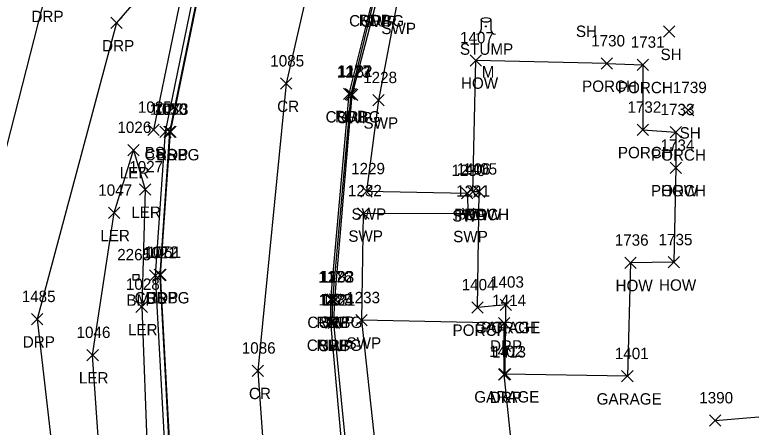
# Model space of a CAD drawing. Extents: x 462930 to 463548, y 29607 to 30453.
# Drawn here: x 463320.55 to 463360, y 30081.35 to 30103.46 of the extents above; entities that cross this region are included whole.
import ezdxf

# ---------------------------------------------------------------- set-up
doc = ezdxf.new("R2010")
doc.units = 0
for name, color, linetype in [('C_A', 7, 'Continuous'), ('C_I', 7, 'Continuous'), ('CPBM', 7, 'Continuous'), ('L_A', 7, 'Continuous'), ('L_C', 7, 'Continuous'), ('L_I', 7, 'Continuous'), ('L_TIC', 7, 'Continuous'), ('LAHR', 7, 'Continuous'), ('LARO', 7, 'Continuous'), ('LBC', 7, 'Continuous'), ('LBF', 7, 'Continuous'), ('LELB', 7, 'Continuous'), ('LTS', 7, 'Continuous'), ('P_A', 7, 'Continuous'), ('P_I', 7, 'Continuous'), ('P_TIC', 7, 'Continuous'), ('PET', 7, 'Continuous'), ('PRC', 7, 'Continuous'), ('R_A', 7, 'Continuous'), ('R_I', 7, 'Continuous'), ('R_TIC', 7, 'Continuous'), ('RC', 7, 'Continuous'), ('RDP', 7, 'Continuous'), ('RSW', 7, 'Continuous')]:
    doc.layers.add(name, color=color, linetype=linetype)

msp = doc.modelspace()

# ---------------------------------------------------------------- linework, layer by layer
at = {"layer": 'CPBM'}
for p, q in [((463326.897, 30089.234), (463326.897, 30089.539)), ((463326.897, 30089.539), (463327.202, 30089.539)), ((463327.05, 30089.387), (463327.05, 30089.387)), ((463327.05, 30089.387), (463327.05, 30089.387)), ((463327.202, 30089.539), (463327.202, 30089.234)), ((463327.202, 30089.234), (463326.897, 30089.234))]:
    msp.add_line(p, q, dxfattribs=at)
at = {"layer": 'L_TIC'}
for points in [[(463355.299, 30102.249), (463355.909, 30102.859)], [(463355.909, 30102.249), (463355.299, 30102.859)], [(463344.945, 30100.709), (463345.555, 30101.319)], [(463345.555, 30100.709), (463344.945, 30101.319)], [(463351.97, 30100.543), (463352.58, 30101.153)], [(463352.58, 30100.543), (463351.97, 30101.153)], [(463353.889, 30100.472), (463354.499, 30101.082)], [(463354.499, 30100.472), (463353.889, 30101.082)], [(463356.324, 30098.042), (463356.934, 30098.652)], [(463356.934, 30098.042), (463356.324, 30098.652)], [(463327.689, 30096.984), (463328.299, 30097.594)], [(463328.299, 30096.984), (463327.689, 30097.594)], [(463353.888, 30096.988), (463354.498, 30097.598)], [(463354.498, 30096.988), (463353.888, 30097.598)], [(463328.322, 30096.879), (463328.932, 30097.489)], [(463328.932, 30096.879), (463328.322, 30097.489)], [(463355.662, 30096.859), (463356.272, 30097.469)], [(463356.272, 30096.859), (463355.662, 30097.469)], [(463326.609, 30095.904), (463327.219, 30096.514)], [(463327.219, 30095.904), (463326.609, 30096.514)], [(463355.66, 30094.946), (463356.27, 30095.556)], [(463356.27, 30094.946), (463355.66, 30095.556)], [(463355.66, 30094.946), (463356.27, 30095.556)], [(463356.27, 30094.946), (463355.66, 30095.556)], [(463327.228, 30093.792), (463327.838, 30094.402)], [(463327.838, 30093.792), (463327.228, 30094.402)], [(463344.785, 30093.669), (463345.395, 30094.279)], [(463345.395, 30093.669), (463344.785, 30094.279)], [(463345.118, 30093.673), (463345.728, 30094.283)], [(463345.728, 30093.673), (463345.118, 30094.283)], [(463345.118, 30093.673), (463345.728, 30094.283)], [(463345.728, 30093.673), (463345.118, 30094.283)], [(463325.568, 30092.541), (463326.178, 30093.151)], [(463326.178, 30092.541), (463325.568, 30093.151)], [(463355.555, 30089.889), (463356.165, 30090.499)], [(463356.165, 30089.889), (463355.555, 30090.499)], [(463353.224, 30089.864), (463353.834, 30090.474)], [(463353.834, 30089.864), (463353.224, 30090.474)], [(463327.781, 30089.182), (463328.391, 30089.792)], [(463328.391, 30089.182), (463327.781, 30089.792)], [(463346.553, 30087.615), (463347.163, 30088.225)], [(463347.163, 30087.615), (463346.553, 30088.225)], [(463346.553, 30087.615), (463347.163, 30088.225)], [(463347.163, 30087.615), (463346.553, 30088.225)], [(463327.049, 30087.499), (463327.659, 30088.109)], [(463327.659, 30087.499), (463327.049, 30088.109)], [(463345.033, 30087.471), (463345.643, 30088.081)], [(463345.643, 30087.471), (463345.033, 30088.081)], [(463324.422, 30084.919), (463325.032, 30085.529)], [(463325.032, 30084.919), (463324.422, 30085.529)], [(463346.509, 30083.898), (463347.119, 30084.508)], [(463347.119, 30083.898), (463346.509, 30084.508)], [(463353.062, 30083.787), (463353.672, 30084.397)], [(463353.672, 30083.787), (463353.062, 30084.397)], [(463357.76, 30081.414), (463358.37, 30082.024)], [(463358.37, 30081.414), (463357.76, 30082.024)]]:
    msp.add_lwpolyline(points, dxfattribs=at)
at = {"layer": 'LAHR'}
msp.add_lwpolyline([(463358.065, 30081.719), (463367.2, 30082.486)], dxfattribs=at)
at = {"layer": 'LARO'}
for points in [[(463325.873, 30092.846), (463326.914, 30096.209)], [(463326.914, 30096.209), (463327.533, 30094.097), (463327.354, 30087.804), (463327.66, 30079.621), (463329.744, 30068.213), (463329.537, 30065.888), (463331.712, 30059.015), (463332.481, 30053.119), (463334.222, 30044.659), (463330.985, 30039.873), (463329.046, 30039.945), (463328.631, 30049.54), (463329.172, 30060.23), (463327.01, 30065.344)], [(463325.38, 30075.731), (463324.727, 30085.224), (463325.873, 30092.846)]]:
    msp.add_lwpolyline(points, dxfattribs=at)
at = {"layer": 'LBC'}
for points in [[(463345.423, 30093.978), (463345.09, 30093.974), (463345.25, 30101.014)], [(463355.965, 30095.251), (463355.86, 30090.194), (463353.529, 30090.169)], [(463353.529, 30090.169), (463353.367, 30084.092)], [(463353.367, 30084.092), (463346.814, 30084.203), (463346.858, 30087.92)]]:
    msp.add_lwpolyline(points, dxfattribs=at)
at = {"layer": 'LBF'}
for points in [[(463352.275, 30100.848), (463345.25, 30101.014)], [(463352.275, 30100.848), (463354.194, 30100.777), (463354.193, 30097.293), (463355.967, 30097.164), (463355.965, 30095.251)], [(463346.858, 30087.92), (463345.338, 30087.776), (463345.423, 30093.978)]]:
    msp.add_lwpolyline(points, dxfattribs=at)
at = {"layer": 'LELB'}
msp.add_lwpolyline([(463338.373, 30022.22), (463340.767, 30011.24), (463345.965, 29995.767), (463346.937, 29987.36), (463347.521, 29987.525), (463346.646, 29996.093), (463342.063, 30011.435), (463339.344, 30022.565), (463336.301, 30037.573), (463333.414, 30053.384), (463330.633, 30068.275), (463328.629, 30079.728), (463328.086, 30089.487), (463328.627, 30097.184), (463330.299, 30105.361), (463329.682, 30105.522), (463327.994, 30097.289)], dxfattribs=at)
at = {"layer": 'LTS'}
for p, q in [((463345.54, 30103.184), (463345.54, 30102.676)), ((463346.048, 30103.134), (463346.048, 30103.184)), ((463346.048, 30103.184), (463346.048, 30102.676)), ((463345.794, 30102.836), (463345.794, 30102.836)), ((463345.794, 30102.836), (463345.794, 30102.836)), ((463345.794, 30102.829), (463345.794, 30102.829))]:
    msp.add_line(p, q, dxfattribs=at)
msp.add_circle((463345.794, 30102.836), 0.0254, dxfattribs=at)
for centre, start, end in [((463345.286, 30102.676), 270, 360), ((463346.302, 30102.676), 180, 270)]:
    msp.add_arc(centre, 0.254, start, end, dxfattribs=at)
msp.add_ellipse((463345.794, 30103.184), major_axis=(-0.254, 0), ratio=0.5, dxfattribs=at)
at = {"layer": 'P_TIC'}
for points in [[(463334.782, 30099.466), (463335.392, 30100.076)], [(463335.392, 30099.466), (463334.782, 30100.076)], [(463338.169, 30098.921), (463338.779, 30099.531)], [(463338.779, 30098.921), (463338.169, 30099.531)], [(463328.587, 30096.878), (463329.197, 30097.488)], [(463329.197, 30096.878), (463328.587, 30097.488)], [(463328.052, 30089.217), (463328.662, 30089.827)], [(463328.662, 30089.217), (463328.052, 30089.827)], [(463337.174, 30087.891), (463337.784, 30088.501)], [(463337.784, 30087.891), (463337.174, 30088.501)], [(463337.175, 30086.663), (463337.785, 30087.273)], [(463337.785, 30086.663), (463337.175, 30087.273)], [(463333.271, 30084.08), (463333.881, 30084.69)], [(463333.881, 30084.08), (463333.271, 30084.69)]]:
    msp.add_lwpolyline(points, dxfattribs=at)
at = {"layer": 'PET'}
for points in [[(463374.338, 29956.391), (463367.555, 29969.533), (463365.556, 29974.625), (463364.583, 29976.896), (463356.695, 29995.475), (463352.505, 30009.098), (463350.167, 30017.966), (463347.98, 30027.115), (463347.733, 30028.32), (463346.051, 30037.294), (463343.907, 30048.483), (463342.761, 30054.643), (463342.551, 30055.85), (463341.301, 30062.483), (463338.432, 30077.399), (463338.227, 30078.623), (463337.48, 30086.968), (463337.479, 30088.196), (463338.474, 30099.226), (463339.751, 30104.374), (463341.961, 30110.783)], [(463349.052, 29990.82), (463346.99, 29996.409), (463342.314, 30011.546), (463339.633, 30022.646), (463336.631, 30037.644), (463333.669, 30053.397), (463330.887, 30068.339), (463328.89, 30079.76), (463328.357, 30089.522), (463328.892, 30097.183), (463330.561, 30105.3)]]:
    msp.add_lwpolyline(points, dxfattribs=at)
at = {"layer": 'PRC'}
msp.add_lwpolyline([(463337.978, 30112.385), (463335.087, 30099.771), (463333.576, 30084.385), (463334.686, 30068.796), (463337.03, 30053.748), (463339.908, 30038.01), (463343.632, 30023.045), (463346.617, 30012.904), (463351.044, 29997.524), (463354.76, 29987.177), (463360.584, 29974.202), (463367.548, 29960.534), (463374.695, 29948.349)], dxfattribs=at)
at = {"layer": 'R_TIC'}
for points in [[(463325.696, 30102.715), (463326.306, 30103.325)], [(463326.306, 30102.715), (463325.696, 30103.325)], [(463338.245, 30098.902), (463338.855, 30099.512)], [(463338.855, 30098.902), (463338.245, 30099.512)], [(463338.325, 30098.865), (463338.935, 30099.475)], [(463338.935, 30098.865), (463338.325, 30099.475)], [(463339.733, 30098.574), (463340.343, 30099.184)], [(463340.343, 30098.574), (463339.733, 30099.184)], [(463328.546, 30096.874), (463329.156, 30097.484)], [(463329.156, 30096.874), (463328.546, 30097.484)], [(463339.089, 30093.692), (463339.699, 30094.302)], [(463339.699, 30093.692), (463339.089, 30094.302)], [(463344.485, 30093.597), (463345.095, 30094.207)], [(463345.095, 30093.597), (463344.485, 30094.207)], [(463338.92, 30092.511), (463339.53, 30093.121)], [(463339.53, 30092.511), (463338.92, 30093.121)], [(463344.537, 30092.489), (463345.147, 30093.099)], [(463345.147, 30092.489), (463344.537, 30093.099)], [(463328.014, 30089.208), (463328.624, 30089.818)], [(463328.624, 30089.208), (463328.014, 30089.818)], [(463337.268, 30087.891), (463337.878, 30088.501)], [(463337.878, 30087.891), (463337.268, 30088.501)], [(463337.402, 30087.899), (463338.012, 30088.509)], [(463338.012, 30087.899), (463337.402, 30088.509)], [(463321.445, 30086.843), (463322.055, 30087.453)], [(463322.055, 30086.843), (463321.445, 30087.453)], [(463338.823, 30086.782), (463339.433, 30087.392)], [(463339.433, 30086.782), (463338.823, 30087.392)], [(463337.24, 30086.663), (463337.85, 30087.273)], [(463337.85, 30086.663), (463337.24, 30087.273)], [(463337.338, 30086.642), (463337.948, 30087.252)], [(463337.948, 30086.642), (463337.338, 30087.252)], [(463346.471, 30086.626), (463347.081, 30087.236)], [(463347.081, 30086.626), (463346.471, 30087.236)], [(463346.465, 30083.871), (463347.075, 30084.481)], [(463347.075, 30083.871), (463346.465, 30084.481)]]:
    msp.add_lwpolyline(points, dxfattribs=at)
at = {"layer": 'RC'}
for points in [[(463341.996, 30110.77), (463339.811, 30104.355), (463338.55, 30099.207), (463337.573, 30088.196), (463337.545, 30086.968)], [(463330.433, 30105.335), (463330.506, 30105.311), (463328.851, 30097.179), (463328.319, 30089.513), (463328.85, 30079.744), (463330.845, 30068.328), (463333.629, 30053.397), (463336.583, 30037.649), (463339.548, 30022.613), (463342.224, 30011.501), (463346.871, 29996.398), (463346.791, 29996.353)]]:
    msp.add_lwpolyline(points, dxfattribs=at)
at = {"layer": 'RDP'}
for points in [[(463319.513, 30094.018), (463322.216, 30104.589), (463322.678, 30111.184), (463317.965, 30116.023), (463310.345, 30118.227), (463299.708, 30118.434), (463291.709, 30117.924)], [(463329.61, 30107.203), (463326.001, 30103.02), (463321.75, 30087.148), (463322.748, 30078.455), (463323.504, 30066.246), (463318.638, 30068.319), (463319.452, 30074.807), (463317.191, 30075.893), (463318.57, 30082.354), (463317.087, 30083.2)], [(463346.776, 30086.931), (463339.128, 30087.087)], [(463347.244, 30079.588), (463346.77, 30084.176), (463346.776, 30086.931)]]:
    msp.add_lwpolyline(points, dxfattribs=at)
at = {"layer": 'RSW'}
for points in [[(463342.697, 30055.906), (463341.529, 30062.506), (463341.211, 30063.796), (463339.622, 30072.17), (463338.628, 30077.431), (463338.465, 30078.663), (463337.643, 30086.947), (463337.707, 30088.204), (463338.63, 30099.17), (463339.961, 30104.318)], [(463340.994, 30103.946), (463340.038, 30098.879), (463339.394, 30093.997), (463344.79, 30093.902), (463344.842, 30092.794), (463339.225, 30092.816), (463339.128, 30087.087), (463340.013, 30078.853), (463340.331, 30075.79), (463340.629, 30074.836), (463341.063, 30072.45), (463344.869, 30072.982), (463344.993, 30071.83), (463341.3, 30071.156), (463343.219, 30061.394), (463344.068, 30056.729)]]:
    msp.add_lwpolyline(points, dxfattribs=at)

# ---------------------------------------------------------------- texts
at = {"layer": 'C_A'}
msp.add_text('BM', height=0.6096, dxfattribs=at).set_placement((463326.536, 30087.863))
at = {"layer": 'C_I'}
msp.add_text('2265', height=0.6096, dxfattribs=at).set_placement((463326.042, 30090.301))
at = {"layer": 'L_A'}
for s, p in [('SH', (463350.612, 30102.268)), ('STUMP', (463344.399, 30101.313)), ('SH', (463355.143, 30101.03)), ('HOW', (463344.453, 30099.49)), ('PORCH', (463350.941, 30099.324)), ('PORCH', (463352.86, 30099.253)), ('SH', (463356.168, 30096.823)), ('BS', (463327.519, 30095.765)), ('BS', (463328.152, 30095.66)), ('PORCH', (463352.859, 30095.769)), ('PORCH', (463354.633, 30095.64)), ('LER', (463326.177, 30094.685)), ('PORCH', (463354.631, 30093.727)), ('HOW', (463355.168, 30093.727)), ('LER', (463326.796, 30092.573)), ('PORCH', (463344.089, 30092.454)), ('HOW', (463344.293, 30092.45)), ('HOW', (463344.626, 30092.454)), ('LER', (463325.136, 30091.322)), ('HOW', (463352.732, 30088.645)), ('HOW', (463355.063, 30088.67)), ('BS', (463327.611, 30087.963)), ('GARAGE', (463345.212, 30086.396)), ('PORCH', (463345.524, 30086.396)), ('LER', (463326.617, 30086.28)), ('PORCH', (463344.004, 30086.252)), ('LER', (463323.99, 30083.7)), ('GARAGE', (463345.168, 30082.679)), ('GARAGE', (463351.721, 30082.568))]:
    msp.add_text(s, height=0.6096, dxfattribs=at).set_placement(p)
at = {"layer": 'L_C'}
msp.add_text('M', height=0.61, dxfattribs=at).set_placement((463345.567, 30100.094))
at = {"layer": 'L_I'}
for s, p in [('1407', (463344.405, 30101.928)), ('1730', (463351.428, 30101.762)), ('1731', (463353.546, 30101.691)), ('1739', (463355.806, 30099.261)), ('1025', (463327.149, 30098.203)), ('1732', (463353.372, 30098.207)), ('1022', (463327.782, 30098.098)), ('1733', (463355.146, 30098.078)), ('1026', (463326.052, 30097.123)), ('1734', (463355.144, 30096.165)), ('1734', (463355.144, 30096.165)), ('1027', (463326.688, 30095.011)), ('1406', (463344.228, 30094.888)), ('1405', (463344.578, 30094.892)), ('1405', (463344.578, 30094.892)), ('1047', (463325.028, 30093.76)), ('1736', (463352.691, 30091.083)), ('1735', (463355.039, 30091.108)), ('1021', (463327.414, 30090.401)), ('1028', (463326.509, 30088.718)), ('1404', (463344.493, 30088.69)), ('1403', (463346.013, 30088.834)), ('1403', (463346.013, 30088.834)), ('1046', (463323.865, 30086.138)), ('1402', (463345.969, 30085.117)), ('1401', (463352.695, 30085.006)), ('1390', (463357.218, 30082.633))]:
    msp.add_text(s, height=0.6096, dxfattribs=at).set_placement(p)
at = {"layer": 'P_A'}
for s, p in [('RDP', (463338.985, 30102.85)), ('CR', (463334.609, 30098.247)), ('RDP', (463337.708, 30097.702)), ('RDP', (463328.126, 30095.659)), ('RDP', (463327.591, 30087.998)), ('RDP', (463336.713, 30086.672)), ('RDP', (463336.714, 30085.444)), ('CR', (463333.098, 30082.861))]:
    msp.add_text(s, height=0.6096, dxfattribs=at).set_placement(p)
at = {"layer": 'P_I'}
for s, p in [('1085', (463334.242, 30100.685)), ('1177', (463337.826, 30100.14)), ('1073', (463328.047, 30098.097)), ('1072', (463327.512, 30090.436)), ('1176', (463336.814, 30089.11)), ('1175', (463336.832, 30087.882)), ('1086', (463332.714, 30085.299))]:
    msp.add_text(s, height=0.6096, dxfattribs=at).set_placement(p)
at = {"layer": 'R_A'}
for s, p in [('DRP', (463321.45, 30103.065)), ('CURBG', (463338.465, 30102.831)), ('SWP', (463339.157, 30102.794)), ('SWP', (463340.19, 30102.422)), ('DRP', (463325.235, 30101.496)), ('CURBG', (463337.204, 30097.683)), ('SWP', (463337.826, 30097.646)), ('SWP', (463339.234, 30097.355)), ('CURBG', (463327.505, 30095.655)), ('SWP', (463338.59, 30092.473)), ('SWP', (463343.986, 30092.378)), ('SWP', (463338.421, 30091.292)), ('SWP', (463344.038, 30091.27)), ('CURBG', (463326.973, 30087.989)), ('CURBG', (463336.227, 30086.672)), ('SWP', (463336.903, 30086.68)), ('DRP', (463320.984, 30085.624)), ('SWP', (463338.324, 30085.563)), ('CURBG', (463336.199, 30085.444)), ('SWP', (463336.839, 30085.423)), ('DRP', (463346.01, 30085.407)), ('DRP', (463346.004, 30082.652))]:
    msp.add_text(s, height=0.6096, dxfattribs=at).set_placement(p)
at = {"layer": 'R_I'}
for s, p in [('1223', (463337.809, 30100.084)), ('1182', (463337.902, 30100.121)), ('1228', (463339.217, 30099.793)), ('1050', (463327.98, 30098.093)), ('1229', (463338.571, 30094.911)), ('1230', (463343.943, 30094.816)), ('1232', (463338.404, 30093.73)), ('1231', (463344.194, 30093.708)), ('1051', (463327.647, 30090.427)), ('1222', (463336.886, 30089.118)), ('1183', (463336.925, 30089.11)), ('1485', (463320.929, 30088.062)), ('1233', (463338.307, 30088.001)), ('1184', (463336.897, 30087.882)), ('1221', (463336.995, 30087.861)), ('1414', (463346.128, 30087.845)), ('1413', (463346.122, 30085.09))]:
    msp.add_text(s, height=0.6096, dxfattribs=at).set_placement(p)

doc.saveas('drawing.dxf')
